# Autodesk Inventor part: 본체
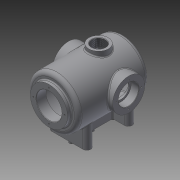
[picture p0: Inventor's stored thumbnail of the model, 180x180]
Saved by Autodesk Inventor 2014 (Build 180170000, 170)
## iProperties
Created: 2016-02
Part Number: 본체
Material: 알루미늄 6061
Document SubType Name: Modeling
Designer: mduedu
Density: 2.71 g/cm^3
Mass: 3247.99 g
Surface Area: 2109.19 cm^2
Volume: 1198.52 cm^3
Appearance: 기본값
Author: mduedu
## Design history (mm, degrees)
sketch "스케치2"
  geometry: L1 (0, 100)-(0, -100); L2 (65, -75.993)-(65, 100); L3 (65, 100)-(0, 100); A1 r 100 centre (0, 0) between (0, -100) and (65, -75.993); 2 further points
  constraints: 6 end point, 2 midpoint, 2 point on circle, 1 centre point, 1 coincident, 1 horizontal, 1 parallel, 1 vertical
  dimensions: "d3" = 200 distance of L1.start L1.end; "d5" = 130 diameter of L2 L1; "d6" = 100 radius of A1
revolve "회전1" sketch "스케치2" stored, may be unused: angle "d7" = 90 deg
sketch "스케치3"
  geometry: C1 r 47.5 at (0, 0); 1 further point
  constraints: 1 centre point, 1 coincident
  dimensions: "d8" = 95 diameter of C1
extrude "돌출2" join sketch "스케치3" distance "d10" = 10; taper "d11" = 0 deg
sketch "스케치5"
  geometry: L1 (47.5, 110)-(47.5, 100) reference; L2 (47.5, 100)-(65, 100) reference; L3 (65, 100)-(65, -75.993) reference; L4 (-65, -75.993)-(-65, 100) reference; L5 (-65, 100)-(-47.5, 100) reference; L6 (-47.5, 100)-(-47.5, 110) reference; L7 (-47.5, 110)-(47.5, 110) reference; L8 (55, 85)-(55, -71.239); L9 (0, 85)-(55, 85); L10 (0, 85)-(0, -90); A1 r 100 centre (0, 0) between (0, -100) and (65, -75.993) reference; A2 r 100 centre (0, 0) between (-65, -75.993) and (0, -100) reference; A3 r 90 centre (0, 0) between (0, -90) and (55, -71.239); 1 further point
  constraints: 6 end point, 2 point on circle, 1 centre point, 1 parallel, 1 perpendicular, 1 point on line, 1 vertical
  dimensions: "d13" = 10 distance between parallel lines of L3 L8; "d14" = 10 radial gap between concentric circles of A3 A1; "d15" = 15 distance between parallel lines of L9 L2
revolve "회전2" sketch "스케치5" stored, may be unused: angle "d16" = 90 deg
hole "구멍1" diameter "d19" = 65; stored, may be unused: countersink angle "d23" = 90 deg, drill point angle "d25" = 118 deg; dims "d17" = 10, "d18" = 10, "d20" = 6, "d21" = 4, "d22" = 2, "d24" = 8
node "작업 평면1"
sketch "스케치6"
  geometry: L1 (47.5, 110)-(-47.5, 110) reference; C1 r 41 at (0, -17); 1 further point
  constraints: 1 centre point, 1 vertical alignment
  dimensions: "d27" = 82 diameter of C1; "d29" = 127 distance from line of C1.centre L1
extrude "돌출3" join sketch "스케치6" stored distance "d30" = 10; taper "d31" = 0 deg
hole "구멍2" diameter "d34" = 42; stored, may be unused: countersink angle "d38" = 90 deg, drill point angle "d40" = 118 deg; dims "d35" = 6, "d36" = 52, "d37" = 20, "d39" = 8, "d180" = 10, "d181" = 10
sketch "스케치7" dims "d41" = 65
  geometry: C1 r 41 at (0, 0) reference; 3 further points
  constraints: 2 vertical alignment, 1 coincident, 2 other
hole "구멍3" sketch "스케치7" at (0, 32.5) diameter "d43" = 3.242; stored, may be unused: countersink angle "d47" = 90 deg, drill point angle "d49" = 118 deg; dims "d44" = 11, "d45" = 13, "d46" = 18, "d48" = 13
sketch "스케치8" dims "d53" = 80
  geometry: 3 further points
  constraints: 2 vertical alignment, 1 coincident, 2 other
hole "구멍4" sketch "스케치8" at (0, 40) diameter "d56" = 3.242; stored, may be unused: countersink angle "d60" = 90 deg, drill point angle "d62" = 118 deg; dims "d57" = 11, "d58" = 13, "d59" = 18, "d61" = 13
fillet "모깎기1" dims "d66" = 10
fillet "모깎기2" dims "d67" = 3
fillet "모깎기3" dims "d68" = 0.3
chamfer "모따기1" distance "d69" = 1; stored, may be unused: second distance "d70" = 2, angle "d71" = 45 deg
node "작업 평면5"
sketch "스케치10"
  geometry: L1 (-50, -63)-(50, -63); L2 (50, -63)-(50, -43); L3 (50, -43)-(-50, -43); L4 (-50, -43)-(-50, -63); L5 (-50, 0)-(50, 0); L6 (-50, 63)-(50, 63); L7 (50, 63)-(50, 43); L8 (50, 43)-(-50, 43); L9 (-50, 43)-(-50, 63); 2 further points
  constraints: 18 end point, 4 symmetric about line, 2 parallel, 2 perpendicular, 1 coincident, 1 horizontal, 1 midpoint
  dimensions: "d80" = 20 distance of L3.end L1.start; "d82" = 100 distance of L1.start L1.end; "d130" = 43 vertical distance of L3.end point (0, 0); "d131" = 50 horizontal distance of L3.end point (0, 0); "d132" = 100 distance of L5.start L5.end
extrude "돌출5" join sketch "스케치10" stored distance "d84" = 10; taper "d85" = 0 deg
sketch "스케치11"
  geometry: L1 (-100, -43)-(-100, 43); L2 (-65, 90)-(-65, -71.239) reference; L3 (-100, -43)-(-41.533, -43) reference; L4 (-100, 43)-(-41.533, 43) reference; 1 further point
  constraints: 2 end point, 1 point on line, 1 vertical
feature "리브1" sketch "스케치11" dims "d88" = 1, "d89" = 20, "d90" = 0, "d91" = 0, "d92" = 1, "d93" = 1
fillet "모깎기12"
fillet "모깎기13"
fillet "모깎기14"
fillet "모깎기15"
fillet "모깎기16" dims "d167" = 3
fillet "모깎기17" dims "d168" = 3
node "작업 평면6"
sketch "스케치19"
  geometry: L1 (77, -58)-(77, 24) reference; L2 (-77, -58)-(-77, 24) reference; L3 (77, -17)-(-77, -17); C1 r 25 at (0, -17); 1 further point
  constraints: 3 midpoint, 2 end point, 1 centre point
  dimensions: "d149" = 50 diameter of C1
extrude "돌출11" join sketch "스케치19" stored distance "d150" = 10; taper "d151" = 0 deg
hole "구멍6" diameter "d154" = 35; stored, may be unused: countersink angle "d158" = 90 deg, drill point angle "d160" = 118 deg; dims "d152" = 10, "d153" = 10, "d155" = 6, "d156" = 4, "d157" = 2, "d159" = 8
fillet "모깎기11" dims "d161" = 3
feature "스레드1" dims "d162" = 10, "d163" = 0
chamfer "모따기3" distance "d164" = 1; stored, may be unused: second distance "d165" = 2, angle "d166" = 45 deg
sketch "스케치20"
  geometry: L1 (10, 40)-(10, -40) reference; L2 (13, -43)-(40, -43) reference; L3 (40, -63)-(-40, -63) reference; L4 (-40, -43)-(-13, -43) reference; L5 (-10, -40)-(-10, 40) reference; L6 (-13, 43)-(-40, 43) reference; L7 (-40, 63)-(40, 63) reference; L8 (40, 43)-(13, 43) reference; L9 (-40, 53)-(40, 53); L10 (-40, -53)-(40, -53); L11 (0, 53)-(0, -53); C1 r 5 at (0, 53); C2 r 5 at (0, 0); C3 r 5 at (0, -53); A1 r 3 centre (13, -40) between (10, -40) and (13, -43) reference; A2 r 10 centre (40, -53) between (40, -63) and (40, -43) reference; A3 r 10 centre (-40, -53) between (-40, -43) and (-40, -63) reference; A4 r 3 centre (-13, -40) between (-13, -43) and (-10, -40) reference; A5 r 3 centre (-13, 40) between (-10, 40) and (-13, 43) reference; A6 r 10 centre (-40, 53) between (-40, 63) and (-40, 43) reference; A7 r 10 centre (40, 53) between (40, 43) and (40, 63) reference; A8 r 3 centre (13, 40) between (13, 43) and (10, 40) reference; 1 further point
  constraints: 6 end point, 3 centre point, 3 coincident, 2 midpoint, 2 parallel
  dimensions: "d169" = 10 diameter of C1; "d170" = 10 diameter of C2; "d171" = 10 diameter of C3
extrude "돌출12" join sketch "스케치20" distance "d172" = 10; taper "d173" = 0 deg
chamfer "모따기4" distance "d174" = 1; stored, may be unused: second distance "d175" = 2, angle "d176" = 45 deg
node "솔리드2"
pattern_circular "원형 패턴1" dims angle "d51" = 360 deg
mirror "대칭1"
pattern_circular "원형 패턴2" dims angle "d64" = 360 deg
node "절단 모서리 투영1"
node "절단 모서리 투영4"
other parameters: "d26" = 77, "d136" = 175
